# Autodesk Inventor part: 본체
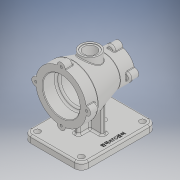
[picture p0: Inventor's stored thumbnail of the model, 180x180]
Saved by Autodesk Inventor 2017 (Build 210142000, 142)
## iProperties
Part Number: 본체
Material: 일반
Document SubType Name: Modeling
Designer: 7-1
Density: 1 g/cm^3
Appearance: 기본값
Author: 7-1
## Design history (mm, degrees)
sketch "스케치1"
  geometry: L1 (-50, 0)-(50, 0); L2 (-50, 0)-(-50, 44); L3 (-50, 44)-(-30, 44); L4 (-30, 44)-(25, 27.5); L5 (25, 27.5)-(50, 27.5); L6 (50, 27.5)-(50, 0); 2 further points
  constraints: 12 end point, 2 perpendicular, 1 coincident, 1 horizontal, 1 midpoint, 1 parallel, 1 vertical
  dimensions: "d0" = 88 diameter of L3 L1; "d1" = 55 diameter of L5 L1; "d2" = 100 distance of L1.start L1.end; "d3" = 20 distance of L2.end L3.end; "d5" = 25 distance of L4.end L5.end
revolve "회전1" sketch "스케치1" stored, may be unused: angle "d6" = 90 deg
node "작업 평면1"
sketch "스케치2"
  geometry: L1 (65, -50)-(-65, -50); L2 (-65, -50)-(-65, 50); L3 (-65, 50)-(65, 50); L4 (65, 50)-(65, -50); 3 further points
  constraints: 8 end point, 2 midpoint, 2 parallel, 1 horizontal, 1 horizontal alignment, 1 perpendicular, 1 vertical alignment
  dimensions: "d8" = 130 distance of L1.start L1.end; "d9" = 100 distance of L1.end L2.end
extrude "돌출1" join sketch "스케치2" distance "d10" = 12; taper "d11" = 0 deg
sketch "스케치3"
  geometry: L1 (4, -25)-(-4, -25); L2 (-4, -25)-(-4, 25); L3 (-4, 25)-(4, 25); L4 (4, 25)-(4, -25); L5 (4, -25)-(-4, 25); L6 (-4, -25)-(4, 25); L7 (24, 4)-(-24, 4); L8 (-24, 4)-(-24, -4); L9 (-24, -4)-(24, -4); L10 (24, -4)-(24, 4); L11 (24, 4)-(-24, -4); L12 (-24, 4)-(24, -4); 1 further point
  constraints: 24 end point, 4 midpoint, 4 parallel, 2 horizontal, 2 perpendicular
  dimensions: "d12" = 8 distance of L2.end L3.end; "d13" = 8 distance of L9.end L7.start; "d14" = 48 distance of L8.end L9.end; "d15" = 50 distance of L3.end L1.start
extrude "돌출2" join sketch "스케치3" stored distance "d16" = 12; taper "d17" = 0 deg
sketch "스케치4"
  geometry: L1 (-50, 0)-(50, 0); L2 (-50, -44)-(-50, 44) reference; L3 (50, -27.5)-(50, 27.5) reference; L4 (-50, 0)-(-50, 32); L5 (-50, 32)-(-27, 32); L6 (-27, 32)-(-27, 26); L7 (-27, 26)-(20, 26); L8 (20, 26)-(20, 20); L9 (20, 20)-(50, 20); L10 (50, 0)-(50, 20); 2 further points
  constraints: 16 end point, 4 perpendicular, 3 midpoint, 2 horizontal, 2 point on line, 1 coincident, 1 collinear
  dimensions: "d19" = 64 diameter of L5 L1; "d20" = 52 diameter of L7 L1; "d21" = 40 diameter of L9 L1; "d22" = 23 distance of L4.end L5.end; "d23" = 47 distance of L6.end L7.end
revolve "회전2" sketch "스케치4" stored, may be unused: angle "d24" = 90 deg
node "작업 평면2"
sketch "스케치5"
  geometry: C1 r 17 at (0, 0); 1 further point
  constraints: 1 centre point, 1 coincident
  dimensions: "d26" = 34 diameter of C1
extrude "돌출3" join sketch "스케치5" stored distance "d27" = 10; taper "d28" = 0 deg
sketch "스케치6"
  geometry: C1 r 14 at (0, 0); 1 further point
  constraints: 1 centre point, 1 coincident
  dimensions: "d29" = 28 diameter of C1
extrude "돌출4" cut sketch "스케치6" distance "d30" = 1; taper "d31" = 0 deg
sketch "스케치7"
  geometry: C1 r 11 at (0, 0); 1 further point
  constraints: 1 centre point, 1 coincident
  dimensions: "d32" = 22 diameter of C1
extrude "돌출5" cut sketch "스케치7" stored distance "d33" = 1; taper "d34" = 0 deg
sketch "스케치8"
  geometry: L1 (-14, 44)-(14, 44) reference; C1 r 44 at (0, 0) reference; C2 r 7 at (0, 44); 1 further point
  constraints: 1 centre point, 1 midpoint
  dimensions: "d35" = 14 diameter of C2
extrude "돌출6" join sketch "스케치8" distance "d36" = 15; taper "d37" = 0 deg
sketch "스케치9"
  geometry: A1 r 7 centre (0, 0) between (6.978, -0.557) and (-6.978, -0.557) reference; 1 further point
hole "구멍1" sketch "스케치9" at (0, 0) diameter "d38" = 4.134; stored, may be unused: countersink angle "d42" = 90 deg, drill point angle "d44" = 118 deg; dims "d39" = 9, "d40" = 4, "d41" = 2, "d43" = 11
fillet "모깎기1" dims "d45" = 1, "d46" = 3
sketch "스케치10"
  geometry: C1 r 7 at (0, 27.5); 2 further points
  constraints: 2 vertical alignment, 1 centre point, 1 other
  dimensions: "d50" = 14 diameter of C1
extrude "돌출7" join sketch "스케치10" distance "d51" = 15; taper "d52" = 0 deg
sketch "스케치11"
  geometry: C1 r 20 at (0, -27.5) reference; A1 r 27.5 centre (0, -27.5) between (-6.943, -0.891) and (6.943, -0.891) reference; A2 r 7 centre (0, 0) between (6.943, -0.891) and (-6.943, -0.891) reference; 1 further point
hole "구멍2" sketch "스케치11" at (0, 0) diameter "d53" = 4.134; stored, may be unused: countersink angle "d57" = 90 deg, drill point angle "d59" = 118 deg; dims "d54" = 9, "d55" = 4, "d56" = 2, "d58" = 11
fillet "모깎기2" dims "d60" = 1, "d61" = 3
fillet "모깎기3" dims "d65" = 12
sketch "스케치12"
  geometry: L1 (65, 38)-(65, -38) reference; L2 (53, -50)-(-53, -50) reference; L3 (-65, -38)-(-65, 38) reference; L4 (-53, 50)-(53, 50) reference; A1 r 12 centre (53, 38) between (65, 38) and (53, 50) reference; A2 r 12 centre (53, -38) between (53, -50) and (65, -38) reference; A3 r 12 centre (-53, -38) between (-65, -38) and (-53, -50) reference; A4 r 12 centre (-53, 38) between (-53, 50) and (-65, 38) reference; 1 further point
hole "구멍3" sketch "스케치12" at (53, -38), (53, 38), (-53, 38), (-53, -38) diameter "d66" = 10; stored, may be unused: countersink angle "d70" = 90 deg, drill point angle "d72" = 118 deg; dims "d67" = 9, "d68" = 4, "d69" = 2, "d71" = 11
node "작업 평면3"
sketch "스케치13"
  geometry: L1 (-53, -50)-(53, -50) reference; 2 further points
  constraints: 1 vertical alignment, 1 other
  dimensions: "d74" = 10 distance from line of L1 point (0, -40)
feature "엠보싱1" sketch "스케치13" dims "d0" = 88, "d1" = 55, "d2" = 100, "d3" = 20, "d5" = 25, "d12" = 8, "d15" = 50, "d75" = 0.5, "d76" = 0
chamfer "모따기1" distance "d77" = 1; stored, may be unused: second distance "d78" = 2, angle "d79" = 45 deg
fillet "모깎기4" dims "d80" = 3
fillet "모깎기5" dims "d81" = 1
fillet "모깎기6" dims "d82" = 3
fillet "모깎기7" dims "d83" = 3
fillet "모깎기8" dims "d84" = 3
node "솔리드1"
pattern_circular "원형 패턴1" dims angle "d48" = 360 deg
pattern_circular "원형 패턴2" dims angle "d63" = 360 deg
node "투영된 루프1"
node "투영된 루프2"
other parameters: "d7" = -82, "d25" = 45, "d73" = 5
